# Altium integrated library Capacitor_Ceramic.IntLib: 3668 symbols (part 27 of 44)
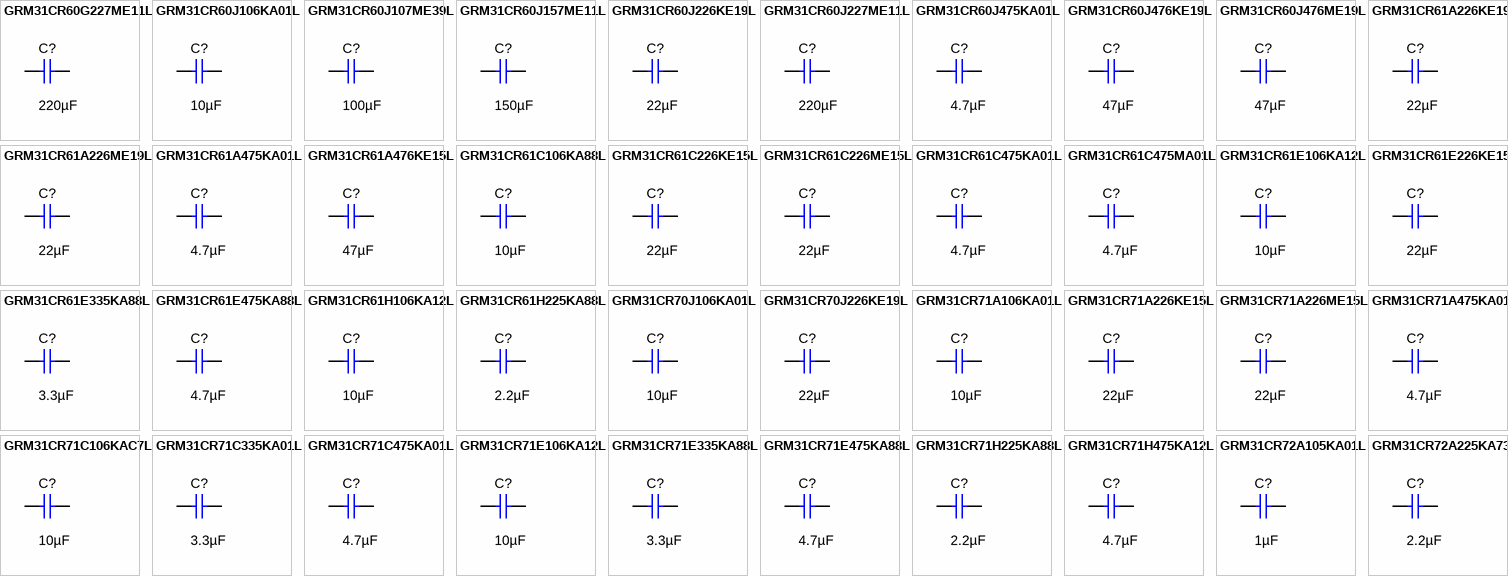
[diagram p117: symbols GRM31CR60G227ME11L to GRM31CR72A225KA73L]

## GRM31CR71H225KA88L
designator C?  ValueDisplayed: 2.2µF  (hidden comment: GRM31CR71H225KA88L)
CAP, CERM, 2.2 µF, 50 V,+/- 10%, X7R, 1206; Manufacturer: MuRata; Polarized: N; CompType: Capacitor; Value: 2.2uF; U/M: EA; Cap_F: 0.0000022; Tolerance_%: 10; VDC_V: 50; Value2: 50V; TaMin_C: -55; TaMax_C: 125; Cap_Case: 1206; SizeArea_mm2: 5.12; SizeAreaWB_mm2: 10.92; SizeX_mm: 3.2; SizeY_mm: 1.6; SizeZ_mm: 1.8; AEC Category: Q200; Green_Lifecycle: Active; Green_REACh: Passed
signal-integrity model Cap
simulation model Cap
footprint 1206_180
footprint 1206_180M
footprint 1206_180L
pins: 1, 2

## GRM31CR71H475KA12L
designator C?  ValueDisplayed: 4.7µF  (hidden comment: GRM31CR71H475KA12L)
CAP, CERM, 4.7 µF, 50 V,+/- 10%, X7R, 1206; Manufacturer: MuRata; Polarized: N; CompType: Capacitor; Value: 4.7uF; U/M: EA; Cap_F: 0.0000047; Tolerance_%: 10; VDC_V: 50; Value2: 50V; TaMin_C: -55; TaMax_C: 125; Cap_Case: 1206; SizeArea_mm2: 5.12; SizeAreaWB_mm2: 10.92; SizeX_mm: 3.2; SizeY_mm: 1.6; SizeZ_mm: 1.8; AEC Category: Q200; Green_Lifecycle: Active; Green_REACh: Passed
signal-integrity model Cap
simulation model Cap
footprint 1206_180
footprint 1206_180M
footprint 1206_180L
pins: 1, 2

## GRM31CR72A105KA01L
designator C?  ValueDisplayed: 1µF  (hidden comment: GRM31CR72A105KA01L)
CAP, CERM, 1 µF, 100 V,+/- 10%, X7R, 1206; Manufacturer: MuRata; Polarized: N; CompType: Capacitor; Value: 1uF; U/M: EA; Cap_F: 0.000001; Tolerance_%: 10; VDC_V: 100; Value2: 100V; TaMin_C: -55; TaMax_C: 125; Cap_Case: 1206; SizeArea_mm2: 5.12; SizeAreaWB_mm2: 10.92; SizeX_mm: 3.2; SizeY_mm: 1.6; SizeZ_mm: 1.8; AEC Category: Q200; Green_Lifecycle: Active; Green_REACh: Passed
signal-integrity model Cap
simulation model Cap
footprint 1206_180
footprint 1206_180M
footprint 1206_180L
pins: 1, 2

## GRM31CR72A225KA73L
designator C?  ValueDisplayed: 2.2µF  (hidden comment: GRM31CR72A225KA73L)
CAP, CERM, 2.2 µF, 100 V,+/- 10%, X7R, 1206; Manufacturer: MuRata; Polarized: N; CompType: Capacitor; Value: 2.2uF; U/M: EA; Cap_F: 0.0000022; Tolerance_%: 10; VDC_V: 100; Value2: 100V; TaMin_C: -55; TaMax_C: 125; Cap_Case: 1206; SizeArea_mm2: 5.12; SizeAreaWB_mm2: 10.92; SizeX_mm: 3.2; SizeY_mm: 1.6; SizeZ_mm: 1.9; AEC Category: Q200; Green_Lifecycle: Active; Green_REACh: Passed
signal-integrity model Cap
simulation model Cap
footprint 1206_190
footprint 1206_190M
footprint 1206_190L
pins: 1, 2

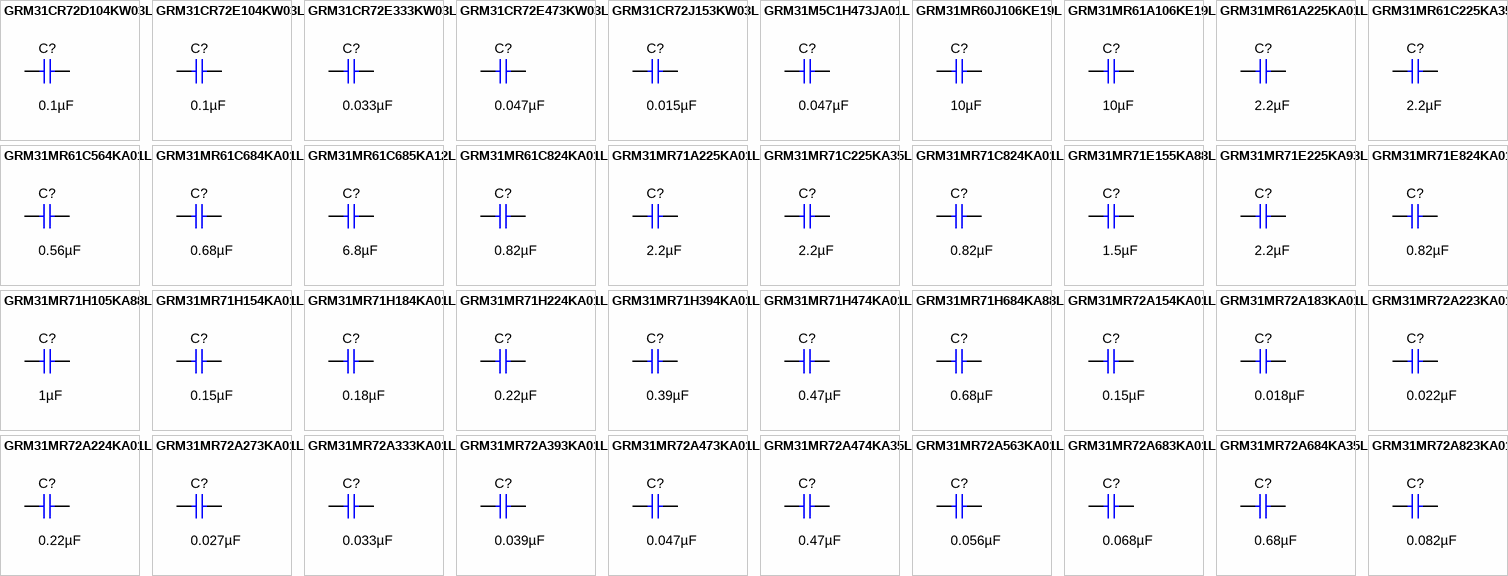
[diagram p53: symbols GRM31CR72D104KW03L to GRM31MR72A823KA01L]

## GRM31CR72D104KW03L
designator C?  ValueDisplayed: 0.1µF  (hidden comment: GRM31CR72D104KW03L)
CAP, CERM, 0.1 µF, 200 V,+/- 10%, X7R, 1206; Manufacturer: MuRata; Polarized: N; CompType: Capacitor; Value: 0.1uF; U/M: EA; Cap_F: 0.0000001; Tolerance_%: 10; VDC_V: 200; Value2: 200V; TaMin_C: -55; TaMax_C: 125; Cap_Case: 1206; SizeArea_mm2: 5.12; SizeAreaWB_mm2: 10.92; SizeX_mm: 3.2; SizeY_mm: 1.6; SizeZ_mm: 1.8; AEC Category: Q200
signal-integrity model Cap
simulation model Cap
footprint 1206_180
footprint 1206_180M
footprint 1206_180L
pins: 1, 2

## GRM31CR72E104KW03L
designator C?  ValueDisplayed: 0.1µF  (hidden comment: GRM31CR72E104KW03L)
CAP, CERM, 0.1 µF, 250 V,+/- 10%, X7R, 1206; Manufacturer: MuRata; Polarized: N; CompType: Capacitor; Value: 0.1uF; U/M: EA; Cap_F: 0.0000001; Tolerance_%: 10; VDC_V: 250; Value2: 250V; TaMin_C: -55; TaMax_C: 125; Cap_Case: 1206; SizeArea_mm2: 5.12; SizeAreaWB_mm2: 10.92; SizeX_mm: 3.2; SizeY_mm: 1.6; SizeZ_mm: 1.8; AEC Category: Q200; Green_Lifecycle: Active; Green_REACh: Passed
signal-integrity model Cap
simulation model Cap
footprint 1206_180
footprint 1206_180M
footprint 1206_180L
pins: 1, 2

## GRM31CR72E333KW03L
designator C?  ValueDisplayed: 0.033µF  (hidden comment: GRM31CR72E333KW03L)
CAP, CERM, 0.033 µF, 250 V,+/- 10%, X7R, 1206; Manufacturer: MuRata; Polarized: N; CompType: Capacitor; Value: 0.033uF; U/M: EA; Cap_F: 0.000000033; Tolerance_%: 10; VDC_V: 250; Value2: 250V; TaMin_C: -55; TaMax_C: 125; Cap_Case: 1206; SizeArea_mm2: 5.12; SizeAreaWB_mm2: 10.92; SizeX_mm: 3.2; SizeY_mm: 1.6; SizeZ_mm: 1.8; AEC Category: Q200
signal-integrity model Cap
simulation model Cap
footprint 1206_180
footprint 1206_180M
footprint 1206_180L
pins: 1, 2

## GRM31CR72E473KW03L
designator C?  ValueDisplayed: 0.047µF  (hidden comment: GRM31CR72E473KW03L)
CAP, CERM, 0.047 µF, 250 V,+/- 10%, X7R, 1206; Manufacturer: MuRata; Polarized: N; CompType: Capacitor; Value: 0.047uF; U/M: EA; Cap_F: 0.000000047; Tolerance_%: 10; VDC_V: 250; Value2: 250V; TaMin_C: -55; TaMax_C: 125; Cap_Case: 1206; SizeArea_mm2: 5.12; SizeAreaWB_mm2: 10.92; SizeX_mm: 3.2; SizeY_mm: 1.6; SizeZ_mm: 1.8; AEC Category: Q200
signal-integrity model Cap
simulation model Cap
footprint 1206_180
footprint 1206_180M
footprint 1206_180L
pins: 1, 2

## GRM31CR72J153KW03L
designator C?  ValueDisplayed: 0.015µF  (hidden comment: GRM31CR72J153KW03L)
CAP, CERM, 0.015 µF, 630 V,+/- 10%, X7R, 1206; Manufacturer: MuRata; Polarized: N; CompType: Capacitor; Value: 0.015uF; U/M: EA; Cap_F: 0.000000015; Tolerance_%: 10; VDC_V: 630; Value2: 630V; TaMin_C: -55; TaMax_C: 125; Cap_Case: 1206; SizeArea_mm2: 5.12; SizeAreaWB_mm2: 10.92; SizeX_mm: 3.2; SizeY_mm: 1.6; SizeZ_mm: 1.8; AEC Category: Q200
signal-integrity model Cap
simulation model Cap
footprint 1206_180
footprint 1206_180M
footprint 1206_180L
pins: 1, 2

## GRM31M5C1H473JA01L
designator C?  ValueDisplayed: 0.047µF  (hidden comment: GRM31M5C1H473JA01L)
CAP, CERM, 0.047 µF, 50 V,+/- 5%, C0G/NP0, 1206; Manufacturer: MuRata; Polarized: N; CompType: Capacitor; Value: 0.047uF; U/M: EA; Cap_F: 0.000000047; Tolerance_%: 5; VDC_V: 50; Value2: 50V; TaMin_C: -55; TaMax_C: 125; Cap_Case: 1206; SizeArea_mm2: 5.12; SizeAreaWB_mm2: 10.92; SizeX_mm: 3.2; SizeY_mm: 1.6; SizeZ_mm: 1.35; AEC Category: Q200; Green_Lifecycle: Active; Green_REACh: Passed
signal-integrity model Cap
simulation model Cap
footprint 1206
footprint 1206M
footprint 1206L
pins: 1, 2

## GRM31MR60J106KE19L
designator C?  ValueDisplayed: 10µF  (hidden comment: GRM31MR60J106KE19L)
CAP, CERM, 10 µF, 6.3 V,+/- 10%, X5R, 1206; Manufacturer: MuRata; Polarized: N; CompType: Capacitor; Value: 10uF; U/M: EA; Cap_F: 0.00001; Tolerance_%: 10; ESR_ohm: 0.005; Value1: 0.005 ohm; VDC_V: 6.3; Value2: 6.3V; TaMin_C: -55; TaMax_C: 85; Cap_Case: 1206; SizeArea_mm2: 5.12; SizeAreaWB_mm2: 10.92; SizeX_mm: 3.2; SizeY_mm: 1.6; SizeZ_mm: 1.35; AEC Category: Q200
signal-integrity model Cap
simulation model Cap
footprint 1206
footprint 1206M
footprint 1206L
pins: 1, 2

## GRM31MR61A106KE19L
designator C?  ValueDisplayed: 10µF  (hidden comment: GRM31MR61A106KE19L)
CAP, CERM, 10 µF, 10 V,+/- 10%, X5R, 1206; Manufacturer: MuRata; Polarized: N; CompType: Capacitor; Value: 10uF; U/M: EA; Cap_F: 0.00001; Tolerance_%: 10; Value2: 10V; TaMin_C: -55; TaMax_C: 85; Cap_Case: 1206; SizeArea_mm2: 5.12; SizeAreaWB_mm2: 10.92; SizeX_mm: 3.2; SizeY_mm: 1.6; SizeZ_mm: 1.35; AEC Category: Q200; Green_Lifecycle: Active; Green_REACh: Passed
signal-integrity model Cap
simulation model Cap
footprint 1206
footprint 1206M
footprint 1206L
pins: 1, 2

## GRM31MR61A225KA01L
designator C?  ValueDisplayed: 2.2µF  (hidden comment: GRM31MR61A225KA01L)
CAP, CERM, 2.2 µF, 10 V,+/- 10%, X5R, 1206; Manufacturer: MuRata; Polarized: N; CompType: Capacitor; Value: 2.2uF; U/M: EA; Cap_F: 0.0000022; Tolerance_%: 10; Value2: 10V; TaMin_C: -55; TaMax_C: 85; Cap_Case: 1206; SizeArea_mm2: 5.12; SizeAreaWB_mm2: 10.92; SizeX_mm: 3.2; SizeY_mm: 1.6; SizeZ_mm: 1.35; AEC Category: Q200
signal-integrity model Cap
simulation model Cap
footprint 1206
footprint 1206M
footprint 1206L
pins: 1, 2

## GRM31MR61C225KA35L
designator C?  ValueDisplayed: 2.2µF  (hidden comment: GRM31MR61C225KA35L)
CAP, CERM, 2.2 µF, 16 V,+/- 10%, X5R, 1206; Manufacturer: MuRata; Polarized: N; CompType: Capacitor; Value: 2.2uF; U/M: EA; Cap_F: 0.0000022; Tolerance_%: 10; VDC_V: 16; Value2: 16V; TaMin_C: -55; TaMax_C: 85; Cap_Case: 1206; SizeArea_mm2: 5.12; SizeAreaWB_mm2: 10.92; SizeX_mm: 3.2; SizeY_mm: 1.6; SizeZ_mm: 1.35; AEC Category: Q200
signal-integrity model Cap
simulation model Cap
footprint 1206
footprint 1206M
footprint 1206L
pins: 1, 2

## GRM31MR61C564KA01L
designator C?  ValueDisplayed: 0.56µF  (hidden comment: GRM31MR61C564KA01L)
CAP, CERM, 0.56 µF, 16 V,+/- 10%, X5R, 1206; Manufacturer: MuRata; Polarized: N; CompType: Capacitor; Value: 0.56uF; U/M: EA; Cap_F: 0.00000056; Tolerance_%: 10; VDC_V: 16; Value2: 16V; TaMin_C: -55; TaMax_C: 85; Cap_Case: 1206; SizeArea_mm2: 5.12; SizeAreaWB_mm2: 10.92; SizeX_mm: 3.2; SizeY_mm: 1.6; SizeZ_mm: 1.35; AEC Category: Q200
signal-integrity model Cap
simulation model Cap
footprint 1206
footprint 1206M
footprint 1206L
pins: 1, 2

## GRM31MR61C684KA01L
designator C?  ValueDisplayed: 0.68µF  (hidden comment: GRM31MR61C684KA01L)
CAP, CERM, 0.68 µF, 16 V,+/- 10%, X5R, 1206; Manufacturer: MuRata; Polarized: N; CompType: Capacitor; Value: 0.68uF; U/M: EA; Cap_F: 0.00000068; Tolerance_%: 10; VDC_V: 16; Value2: 16V; TaMin_C: -55; TaMax_C: 85; Cap_Case: 1206; SizeArea_mm2: 5.12; SizeAreaWB_mm2: 10.92; SizeX_mm: 3.2; SizeY_mm: 1.6; SizeZ_mm: 1.35; AEC Category: Q200
signal-integrity model Cap
simulation model Cap
footprint 1206
footprint 1206M
footprint 1206L
pins: 1, 2

## GRM31MR61C685KA12L
designator C?  ValueDisplayed: 6.8µF  (hidden comment: GRM31MR61C685KA12L)
CAP, CERM, 6.8 µF, 16 V,+/- 10%, X5R, 1206; Manufacturer: MuRata; Polarized: N; CompType: Capacitor; Value: 6.8uF; U/M: EA; Cap_F: 0.0000068; Tolerance_%: 10; VDC_V: 16; Value2: 16V; TaMin_C: -55; TaMax_C: 85; Cap_Case: 1206; SizeArea_mm2: 5.12; SizeAreaWB_mm2: 10.92; SizeX_mm: 3.2; SizeY_mm: 1.6; SizeZ_mm: 1.35; AEC Category: Q200
signal-integrity model Cap
simulation model Cap
footprint 1206
footprint 1206M
footprint 1206L
pins: 1, 2

## GRM31MR61C824KA01L
designator C?  ValueDisplayed: 0.82µF  (hidden comment: GRM31MR61C824KA01L)
CAP, CERM, 0.82 µF, 16 V,+/- 10%, X5R, 1206; Manufacturer: MuRata; Polarized: N; CompType: Capacitor; Value: 0.82uF; U/M: EA; Cap_F: 0.00000082; Tolerance_%: 10; VDC_V: 16; Value2: 16V; TaMin_C: -55; TaMax_C: 85; Cap_Case: 1206; SizeArea_mm2: 5.12; SizeAreaWB_mm2: 10.92; SizeX_mm: 3.2; SizeY_mm: 1.6; SizeZ_mm: 1.35; AEC Category: Q200
signal-integrity model Cap
simulation model Cap
footprint 1206
footprint 1206M
footprint 1206L
pins: 1, 2

## GRM31MR71A225KA01L
designator C?  ValueDisplayed: 2.2µF  (hidden comment: GRM31MR71A225KA01L)
CAP, CERM, 2.2 µF, 10 V,+/- 10%, X7R, 1206; Manufacturer: MuRata; Polarized: N; CompType: Capacitor; Value: 2.2uF; U/M: EA; Cap_F: 0.0000022; Tolerance_%: 10; Value2: 10V; TaMin_C: -55; TaMax_C: 125; Cap_Case: 1206; SizeArea_mm2: 5.12; SizeAreaWB_mm2: 10.92; SizeX_mm: 3.2; SizeY_mm: 1.6; SizeZ_mm: 1.35; AEC Category: Q200
signal-integrity model Cap
simulation model Cap
footprint 1206
footprint 1206M
footprint 1206L
pins: 1, 2

## GRM31MR71C225KA35L
designator C?  ValueDisplayed: 2.2µF  (hidden comment: GRM31MR71C225KA35L)
CAP, CERM, 2.2 µF, 16 V,+/- 10%, X7R, 1206; Manufacturer: MuRata; Polarized: N; CompType: Capacitor; Value: 2.2uF; U/M: EA; Cap_F: 0.0000022; Tolerance_%: 10; ESR_ohm: 0.006; Value1: 0.006 ohm; VDC_V: 16; Value2: 16V; TaMin_C: -55; TaMax_C: 125; Cap_Case: 1206; SizeArea_mm2: 5.12; SizeAreaWB_mm2: 10.92; SizeX_mm: 3.2; SizeY_mm: 1.6; SizeZ_mm: 1.35; AEC Category: Q200; Green_Lifecycle: Active; Green_REACh: Passed
signal-integrity model Cap
simulation model Cap
footprint 1206
footprint 1206M
footprint 1206L
pins: 1, 2

## GRM31MR71C824KA01L
designator C?  ValueDisplayed: 0.82µF  (hidden comment: GRM31MR71C824KA01L)
CAP, CERM, 0.82 µF, 16 V,+/- 10%, X7R, 1206; Manufacturer: MuRata; Polarized: N; CompType: Capacitor; Value: 0.82uF; U/M: EA; Cap_F: 0.00000082; Tolerance_%: 10; VDC_V: 16; Value2: 16V; TaMin_C: -55; TaMax_C: 125; Cap_Case: 1206; SizeArea_mm2: 5.12; SizeAreaWB_mm2: 10.92; SizeX_mm: 3.2; SizeY_mm: 1.6; SizeZ_mm: 1.35; AEC Category: Q200
signal-integrity model Cap
simulation model Cap
footprint 1206
footprint 1206M
footprint 1206L
pins: 1, 2

## GRM31MR71E155KA88L
designator C?  ValueDisplayed: 1.5µF  (hidden comment: GRM31MR71E155KA88L)
CAP, CERM, 1.5 µF, 25 V,+/- 10%, X7R, 1206; Manufacturer: MuRata; Polarized: N; CompType: Capacitor; Value: 1.5uF; U/M: EA; Cap_F: 0.0000015; Tolerance_%: 10; VDC_V: 25; Value2: 25V; TaMin_C: -55; TaMax_C: 125; Cap_Case: 1206; SizeArea_mm2: 5.12; SizeAreaWB_mm2: 10.92; SizeX_mm: 3.2; SizeY_mm: 1.6; SizeZ_mm: 1.35; AEC Category: Q200
signal-integrity model Cap
simulation model Cap
footprint 1206
footprint 1206M
footprint 1206L
pins: 1, 2

## GRM31MR71E225KA93L
designator C?  ValueDisplayed: 2.2µF  (hidden comment: GRM31MR71E225KA93L)
CAP, CERM, 2.2 µF, 25 V,+/- 10%, X7R, 1206; Manufacturer: MuRata; Polarized: N; CompType: Capacitor; Value: 2.2uF; U/M: EA; Cap_F: 0.0000022; Tolerance_%: 10; VDC_V: 25; Value2: 25V; TaMin_C: -55; TaMax_C: 125; Cap_Case: 1206; SizeArea_mm2: 5.12; SizeAreaWB_mm2: 10.92; SizeX_mm: 3.2; SizeY_mm: 1.6; SizeZ_mm: 1.35; AEC Category: Q200; Green_Lifecycle: Active; Green_REACh: Passed
signal-integrity model Cap
simulation model Cap
footprint 1206
footprint 1206M
footprint 1206L
pins: 1, 2

## GRM31MR71E824KA01L
designator C?  ValueDisplayed: 0.82µF  (hidden comment: GRM31MR71E824KA01L)
CAP, CERM, 0.82 µF, 25 V,+/- 10%, X7R, 1206; Manufacturer: MuRata; Polarized: N; CompType: Capacitor; Value: 0.82uF; U/M: EA; Cap_F: 0.00000082; Tolerance_%: 10; VDC_V: 25; Value2: 25V; TaMin_C: -55; TaMax_C: 125; Cap_Case: 1206; SizeArea_mm2: 5.12; SizeAreaWB_mm2: 10.92; SizeX_mm: 3.2; SizeY_mm: 1.6; SizeZ_mm: 1.35; AEC Category: Q200
signal-integrity model Cap
simulation model Cap
footprint 1206
footprint 1206M
footprint 1206L
pins: 1, 2

## GRM31MR71H105KA88L
designator C?  ValueDisplayed: 1µF  (hidden comment: GRM31MR71H105KA88L)
CAP, CERM, 1 µF, 50 V,+/- 10%, X7R, 1206; Manufacturer: MuRata; Polarized: N; CompType: Capacitor; Value: 1uF; U/M: EA; Cap_F: 0.000001; Tolerance_%: 10; VDC_V: 50; Value2: 50V; TaMin_C: -55; TaMax_C: 125; Cap_Case: 1206; SizeArea_mm2: 5.12; SizeAreaWB_mm2: 10.92; SizeX_mm: 3.2; SizeY_mm: 1.6; SizeZ_mm: 1.35; AEC Category: Q200; Green_Lifecycle: Active; Green_REACh: Passed
signal-integrity model Cap
simulation model Cap
footprint 1206
footprint 1206M
footprint 1206L
pins: 1, 2

## GRM31MR71H154KA01L
designator C?  ValueDisplayed: 0.15µF  (hidden comment: GRM31MR71H154KA01L)
CAP, CERM, 0.15 µF, 50 V,+/- 10%, X7R, 1206; Manufacturer: MuRata; Polarized: N; CompType: Capacitor; Value: 0.15uF; U/M: EA; Cap_F: 0.00000015; Tolerance_%: 10; VDC_V: 50; Value2: 50V; TaMin_C: -55; TaMax_C: 125; Cap_Case: 1206; SizeArea_mm2: 5.12; SizeAreaWB_mm2: 10.92; SizeX_mm: 3.2; SizeY_mm: 1.6; SizeZ_mm: 1.35; AEC Category: Q200
signal-integrity model Cap
simulation model Cap
footprint 1206
footprint 1206M
footprint 1206L
pins: 1, 2

## GRM31MR71H184KA01L
designator C?  ValueDisplayed: 0.18µF  (hidden comment: GRM31MR71H184KA01L)
CAP, CERM, 0.18 µF, 50 V,+/- 10%, X7R, 1206; Manufacturer: MuRata; Polarized: N; CompType: Capacitor; Value: 0.18uF; U/M: EA; Cap_F: 0.00000018; Tolerance_%: 10; VDC_V: 50; Value2: 50V; TaMin_C: -55; TaMax_C: 125; Cap_Case: 1206; SizeArea_mm2: 5.12; SizeAreaWB_mm2: 10.92; SizeX_mm: 3.2; SizeY_mm: 1.6; SizeZ_mm: 1.35; AEC Category: Q200
signal-integrity model Cap
simulation model Cap
footprint 1206
footprint 1206M
footprint 1206L
pins: 1, 2

## GRM31MR71H224KA01L
designator C?  ValueDisplayed: 0.22µF  (hidden comment: GRM31MR71H224KA01L)
CAP, CERM, 0.22 µF, 50 V,+/- 10%, X7R, 1206; Manufacturer: MuRata; Polarized: N; CompType: Capacitor; Value: 0.22uF; U/M: EA; Cap_F: 0.00000022; Tolerance_%: 10; VDC_V: 50; Value2: 50V; TaMin_C: -55; TaMax_C: 125; Cap_Case: 1206; SizeArea_mm2: 5.12; SizeAreaWB_mm2: 10.92; SizeX_mm: 3.2; SizeY_mm: 1.6; SizeZ_mm: 1.35; AEC Category: Q200
signal-integrity model Cap
simulation model Cap
footprint 1206
footprint 1206M
footprint 1206L
pins: 1, 2

## GRM31MR71H394KA01L
designator C?  ValueDisplayed: 0.39µF  (hidden comment: GRM31MR71H394KA01L)
CAP, CERM, 0.39 µF, 50 V,+/- 10%, X7R, 1206; Manufacturer: MuRata; Polarized: N; CompType: Capacitor; Value: 0.39uF; U/M: EA; Cap_F: 0.00000039; Tolerance_%: 10; VDC_V: 50; Value2: 50V; TaMin_C: -55; TaMax_C: 125; Cap_Case: 1206; SizeArea_mm2: 5.12; SizeAreaWB_mm2: 10.92; SizeX_mm: 3.2; SizeY_mm: 1.6; SizeZ_mm: 1.35; AEC Category: Q200
signal-integrity model Cap
simulation model Cap
footprint 1206
footprint 1206M
footprint 1206L
pins: 1, 2

## GRM31MR71H474KA01L
designator C?  ValueDisplayed: 0.47µF  (hidden comment: GRM31MR71H474KA01L)
CAP, CERM, 0.47 µF, 50 V,+/- 10%, X7R, 1206; Manufacturer: MuRata; Polarized: N; CompType: Capacitor; Value: 0.47uF; U/M: EA; Cap_F: 0.00000047; Tolerance_%: 10; VDC_V: 50; Value2: 50V; TaMin_C: -55; TaMax_C: 125; Cap_Case: 1206; SizeArea_mm2: 5.12; SizeAreaWB_mm2: 10.92; SizeX_mm: 3.2; SizeY_mm: 1.6; SizeZ_mm: 1.35; AEC Category: Q200
signal-integrity model Cap
simulation model Cap
footprint 1206
footprint 1206M
footprint 1206L
pins: 1, 2

## GRM31MR71H684KA88L
designator C?  ValueDisplayed: 0.68µF  (hidden comment: GRM31MR71H684KA88L)
CAP, CERM, 0.68 µF, 50 V,+/- 10%, X7R, 1206; Manufacturer: MuRata; Polarized: N; CompType: Capacitor; Value: 0.68uF; U/M: EA; Cap_F: 0.00000068; Tolerance_%: 10; VDC_V: 50; Value2: 50V; TaMin_C: -55; TaMax_C: 125; Cap_Case: 1206; SizeArea_mm2: 5.12; SizeAreaWB_mm2: 10.92; SizeX_mm: 3.2; SizeY_mm: 1.6; SizeZ_mm: 1.35; AEC Category: Q200; Green_Lifecycle: Active; Green_REACh: Passed
signal-integrity model Cap
simulation model Cap
footprint 1206
footprint 1206M
footprint 1206L
pins: 1, 2

## GRM31MR72A154KA01L
designator C?  ValueDisplayed: 0.15µF  (hidden comment: GRM31MR72A154KA01L)
CAP, CERM, 0.15 µF, 100 V,+/- 10%, X7R, 1206; Manufacturer: MuRata; Polarized: N; CompType: Capacitor; Value: 0.15uF; U/M: EA; Cap_F: 0.00000015; Tolerance_%: 10; VDC_V: 100; Value2: 100V; TaMin_C: -55; TaMax_C: 125; Cap_Case: 1206; SizeArea_mm2: 5.12; SizeAreaWB_mm2: 10.92; SizeX_mm: 3.2; SizeY_mm: 1.6; SizeZ_mm: 1.35; AEC Category: Q200
signal-integrity model Cap
simulation model Cap
footprint 1206
footprint 1206M
footprint 1206L
pins: 1, 2

## GRM31MR72A183KA01L
designator C?  ValueDisplayed: 0.018µF  (hidden comment: GRM31MR72A183KA01L)
CAP, CERM, 0.018 µF, 100 V,+/- 10%, X7R, 1206; Manufacturer: MuRata; Polarized: N; CompType: Capacitor; Value: 0.018uF; U/M: EA; Cap_F: 0.000000018; Tolerance_%: 10; VDC_V: 100; Value2: 100V; TaMin_C: -55; TaMax_C: 125; Cap_Case: 1206; SizeArea_mm2: 5.12; SizeAreaWB_mm2: 10.92; SizeX_mm: 3.2; SizeY_mm: 1.6; SizeZ_mm: 1.35; AEC Category: Q200
signal-integrity model Cap
simulation model Cap
footprint 1206
footprint 1206M
footprint 1206L
pins: 1, 2

## GRM31MR72A223KA01L
designator C?  ValueDisplayed: 0.022µF  (hidden comment: GRM31MR72A223KA01L)
CAP, CERM, 0.022 µF, 100 V,+/- 10%, X7R, 1206; Manufacturer: MuRata; Polarized: N; CompType: Capacitor; Value: 0.022uF; U/M: EA; Cap_F: 0.000000022; Tolerance_%: 10; VDC_V: 100; Value2: 100V; TaMin_C: -55; TaMax_C: 125; Cap_Case: 1206; SizeArea_mm2: 5.12; SizeAreaWB_mm2: 10.92; SizeX_mm: 3.2; SizeY_mm: 1.6; SizeZ_mm: 1.35; AEC Category: Q200
signal-integrity model Cap
simulation model Cap
footprint 1206
footprint 1206M
footprint 1206L
pins: 1, 2

## GRM31MR72A224KA01L
designator C?  ValueDisplayed: 0.22µF  (hidden comment: GRM31MR72A224KA01L)
CAP, CERM, 0.22 µF, 100 V,+/- 10%, X7R, 1206; Manufacturer: MuRata; Polarized: N; CompType: Capacitor; Value: 0.22uF; U/M: EA; Cap_F: 0.00000022; Tolerance_%: 10; VDC_V: 100; Value2: 100V; TaMin_C: -55; TaMax_C: 125; Cap_Case: 1206; SizeArea_mm2: 5.12; SizeAreaWB_mm2: 10.92; SizeX_mm: 3.2; SizeY_mm: 1.6; SizeZ_mm: 1.35; AEC Category: Q200
signal-integrity model Cap
simulation model Cap
footprint 1206
footprint 1206M
footprint 1206L
pins: 1, 2

## GRM31MR72A273KA01L
designator C?  ValueDisplayed: 0.027µF  (hidden comment: GRM31MR72A273KA01L)
CAP, CERM, 0.027 µF, 100 V,+/- 10%, X7R, 1206; Manufacturer: MuRata; Polarized: N; CompType: Capacitor; Value: 0.027uF; U/M: EA; Cap_F: 0.000000027; Tolerance_%: 10; VDC_V: 100; Value2: 100V; TaMin_C: -55; TaMax_C: 125; Cap_Case: 1206; SizeArea_mm2: 5.12; SizeAreaWB_mm2: 10.92; SizeX_mm: 3.2; SizeY_mm: 1.6; SizeZ_mm: 1.35; AEC Category: Q200
signal-integrity model Cap
simulation model Cap
footprint 1206
footprint 1206M
footprint 1206L
pins: 1, 2

## GRM31MR72A333KA01L
designator C?  ValueDisplayed: 0.033µF  (hidden comment: GRM31MR72A333KA01L)
CAP, CERM, 0.033 µF, 100 V,+/- 10%, X7R, 1206; Manufacturer: MuRata; Polarized: N; CompType: Capacitor; Value: 0.033uF; U/M: EA; Cap_F: 0.000000033; Tolerance_%: 10; VDC_V: 100; Value2: 100V; TaMin_C: -55; TaMax_C: 125; Cap_Case: 1206; SizeArea_mm2: 5.12; SizeAreaWB_mm2: 10.92; SizeX_mm: 3.2; SizeY_mm: 1.6; SizeZ_mm: 1.35; AEC Category: Q200
signal-integrity model Cap
simulation model Cap
footprint 1206
footprint 1206M
footprint 1206L
pins: 1, 2

## GRM31MR72A393KA01L
designator C?  ValueDisplayed: 0.039µF  (hidden comment: GRM31MR72A393KA01L)
CAP, CERM, 0.039 µF, 100 V,+/- 10%, X7R, 1206; Manufacturer: MuRata; Polarized: N; CompType: Capacitor; Value: 0.039uF; U/M: EA; Cap_F: 0.000000039; Tolerance_%: 10; VDC_V: 100; Value2: 100V; TaMin_C: -55; TaMax_C: 125; Cap_Case: 1206; SizeArea_mm2: 5.12; SizeAreaWB_mm2: 10.92; SizeX_mm: 3.2; SizeY_mm: 1.6; SizeZ_mm: 1.35; AEC Category: Q200
signal-integrity model Cap
simulation model Cap
footprint 1206
footprint 1206M
footprint 1206L
pins: 1, 2

## GRM31MR72A473KA01L
designator C?  ValueDisplayed: 0.047µF  (hidden comment: GRM31MR72A473KA01L)
CAP, CERM, 0.047 µF, 100 V,+/- 10%, X7R, 1206; Manufacturer: MuRata; Polarized: N; CompType: Capacitor; Value: 0.047uF; U/M: EA; Cap_F: 0.000000047; Tolerance_%: 10; VDC_V: 100; Value2: 100V; TaMin_C: -55; TaMax_C: 125; Cap_Case: 1206; SizeArea_mm2: 5.12; SizeAreaWB_mm2: 10.92; SizeX_mm: 3.2; SizeY_mm: 1.6; SizeZ_mm: 1.35; AEC Category: Q200
signal-integrity model Cap
simulation model Cap
footprint 1206
footprint 1206M
footprint 1206L
pins: 1, 2

## GRM31MR72A474KA35L
designator C?  ValueDisplayed: 0.47µF  (hidden comment: GRM31MR72A474KA35L)
CAP, CERM, 0.47 µF, 100 V,+/- 10%, X7R, 1206; Manufacturer: MuRata; Polarized: N; CompType: Capacitor; Value: 0.47uF; U/M: EA; Cap_F: 0.00000047; Tolerance_%: 10; VDC_V: 100; Value2: 100V; TaMin_C: -55; TaMax_C: 125; Cap_Case: 1206; SizeArea_mm2: 5.12; SizeAreaWB_mm2: 10.92; SizeX_mm: 3.2; SizeY_mm: 1.6; SizeZ_mm: 1.35; AEC Category: Q200
signal-integrity model Cap
simulation model Cap
footprint 1206
footprint 1206M
footprint 1206L
pins: 1, 2

## GRM31MR72A563KA01L
designator C?  ValueDisplayed: 0.056µF  (hidden comment: GRM31MR72A563KA01L)
CAP, CERM, 0.056 µF, 100 V,+/- 10%, X7R, 1206; Manufacturer: MuRata; Polarized: N; CompType: Capacitor; Value: 0.056uF; U/M: EA; Cap_F: 0.000000056; Tolerance_%: 10; VDC_V: 100; Value2: 100V; TaMin_C: -55; TaMax_C: 125; Cap_Case: 1206; SizeArea_mm2: 5.12; SizeAreaWB_mm2: 10.92; SizeX_mm: 3.2; SizeY_mm: 1.6; SizeZ_mm: 1.35; AEC Category: Q200
signal-integrity model Cap
simulation model Cap
footprint 1206
footprint 1206M
footprint 1206L
pins: 1, 2

## GRM31MR72A683KA01L
designator C?  ValueDisplayed: 0.068µF  (hidden comment: GRM31MR72A683KA01L)
CAP, CERM, 0.068 µF, 100 V,+/- 10%, X7R, 1206; Manufacturer: MuRata; Polarized: N; CompType: Capacitor; Value: 0.068uF; U/M: EA; Cap_F: 0.000000068; Tolerance_%: 10; ESR_ohm: 0.01; Value1: 0.01 ohm; VDC_V: 100; Value2: 100V; IRMS_A: 0.8; TaMin_C: -55; TaMax_C: 125; Cap_Case: 1206; SizeArea_mm2: 5.12; SizeAreaWB_mm2: 10.92; SizeX_mm: 3.2; SizeY_mm: 1.6; SizeZ_mm: 1.35; AEC Category: Q200
signal-integrity model Cap
simulation model Cap
footprint 1206
footprint 1206M
footprint 1206L
pins: 1, 2

## GRM31MR72A684KA35L
designator C?  ValueDisplayed: 0.68µF  (hidden comment: GRM31MR72A684KA35L)
CAP, CERM, 0.68 µF, 100 V,+/- 10%, X7R, 1206; Manufacturer: MuRata; Polarized: N; CompType: Capacitor; Value: 0.68uF; U/M: EA; Cap_F: 0.00000068; Tolerance_%: 10; VDC_V: 100; Value2: 100V; TaMin_C: -55; TaMax_C: 125; Cap_Case: 1206; SizeArea_mm2: 5.12; SizeAreaWB_mm2: 10.92; SizeX_mm: 3.2; SizeY_mm: 1.6; SizeZ_mm: 1.35; AEC Category: Q200
signal-integrity model Cap
simulation model Cap
footprint 1206
footprint 1206M
footprint 1206L
pins: 1, 2

## GRM31MR72A823KA01L
designator C?  ValueDisplayed: 0.082µF  (hidden comment: GRM31MR72A823KA01L)
CAP, CERM, 0.082 µF, 100 V,+/- 10%, X7R, 1206; Manufacturer: MuRata; Polarized: N; CompType: Capacitor; Value: 0.082uF; U/M: EA; Cap_F: 0.000000082; Tolerance_%: 10; VDC_V: 100; Value2: 100V; TaMin_C: -55; TaMax_C: 125; Cap_Case: 1206; SizeArea_mm2: 5.12; SizeAreaWB_mm2: 10.92; SizeX_mm: 3.2; SizeY_mm: 1.6; SizeZ_mm: 1.35; AEC Category: Q200
signal-integrity model Cap
simulation model Cap
footprint 1206
footprint 1206M
footprint 1206L
pins: 1, 2

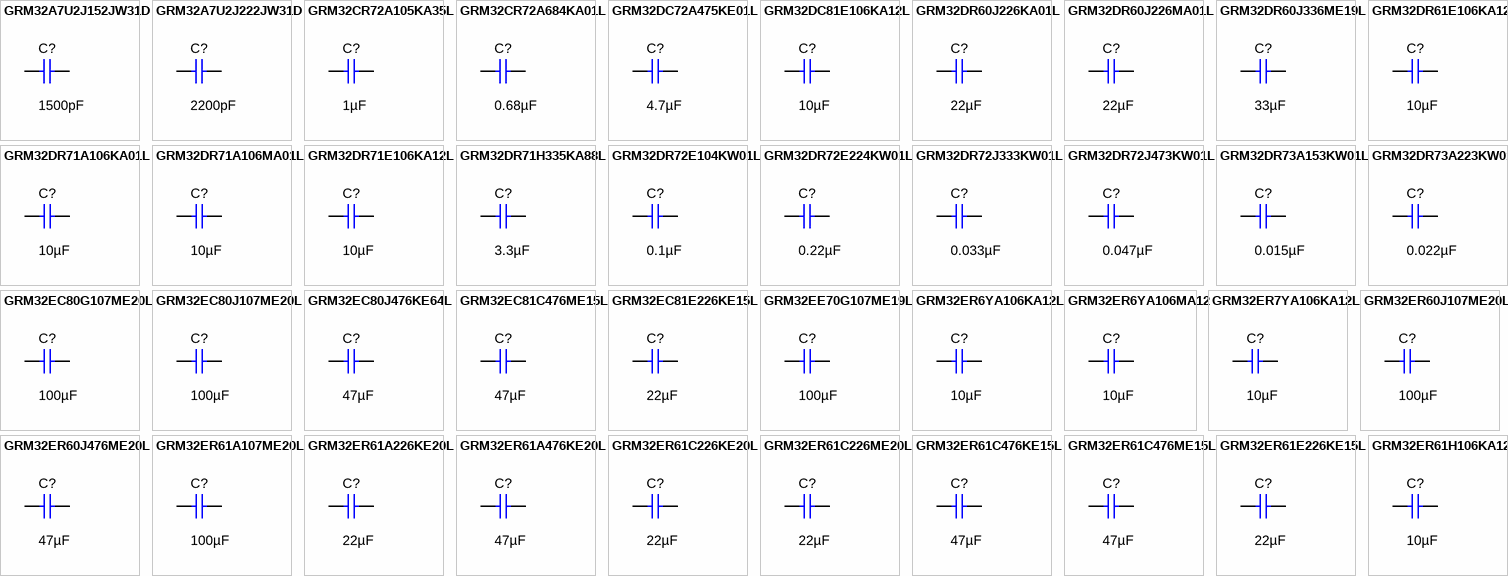
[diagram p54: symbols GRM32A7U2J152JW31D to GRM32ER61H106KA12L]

## GRM32A7U2J152JW31D
designator C?  ValueDisplayed: 1500pF  (hidden comment: GRM32A7U2J152JW31D)
CAP, CERM, 1500 pF, 630 V,+/- 5%, U2J, 1210; Manufacturer: MuRata; Polarized: N; CompType: Capacitor; Value: 1500pF; U/M: EA; Cap_F: 0.0000000015; Tolerance_%: 5; VDC_V: 630; Value2: 630V; TaMin_C: -55; TaMax_C: 125; Cap_Case: 1210; SizeArea_mm2: 8; SizeAreaWB_mm2: 14.7; SizeX_mm: 3.2; SizeY_mm: 2.5; SizeZ_mm: 1.35; AEC Category: Q200
signal-integrity model Cap
simulation model Cap
footprint 1210
footprint 1210M
footprint 1210L
pins: 1, 2

## GRM32A7U2J222JW31D
designator C?  ValueDisplayed: 2200pF  (hidden comment: GRM32A7U2J222JW31D)
CAP, CERM, 2200 pF, 630 V,+/- 5%, U2J, 1210; Manufacturer: MuRata; Polarized: N; CompType: Capacitor; Value: 2200pF; U/M: EA; Cap_F: 0.0000000022; Tolerance_%: 5; VDC_V: 630; Value2: 630V; TaMin_C: -55; TaMax_C: 125; Cap_Case: 1210; SizeArea_mm2: 8; SizeAreaWB_mm2: 14.7; SizeX_mm: 3.2; SizeY_mm: 2.5; SizeZ_mm: 1.35; AEC Category: Q200
signal-integrity model Cap
simulation model Cap
footprint 1210
footprint 1210M
footprint 1210L
pins: 1, 2

## GRM32CR72A105KA35L
designator C?  ValueDisplayed: 1µF  (hidden comment: GRM32CR72A105KA35L)
CAP, CERM, 1 µF, 100 V,+/- 10%, X7R, 1210; Manufacturer: MuRata; Polarized: N; CompType: Capacitor; Value: 1uF; U/M: EA; Cap_F: 0.000001; Tolerance_%: 10; VDC_V: 100; Value2: 100V; TaMin_C: -55; TaMax_C: 125; Cap_Case: 1210; SizeArea_mm2: 8; SizeAreaWB_mm2: 14.7; SizeX_mm: 3.2; SizeY_mm: 2.5; SizeZ_mm: 1.8; AEC Category: Q200; Green_Lifecycle: Active; Green_REACh: Passed
signal-integrity model Cap
simulation model Cap
footprint 1210_180
footprint 1210_180M
footprint 1210_180L
pins: 1, 2

## GRM32CR72A684KA01L
designator C?  ValueDisplayed: 0.68µF  (hidden comment: GRM32CR72A684KA01L)
CAP, CERM, 0.68 µF, 100 V,+/- 10%, X7R, 1210; Manufacturer: MuRata; Polarized: N; CompType: Capacitor; Value: 0.68uF; U/M: EA; Cap_F: 0.00000068; Tolerance_%: 10; VDC_V: 100; Value2: 100V; TaMin_C: -55; TaMax_C: 125; Cap_Case: 1210; SizeArea_mm2: 8; SizeAreaWB_mm2: 14.7; SizeX_mm: 3.2; SizeY_mm: 2.5; SizeZ_mm: 1.8; AEC Category: Q200
signal-integrity model Cap
simulation model Cap
footprint 1210_180
footprint 1210_180M
footprint 1210_180L
pins: 1, 2

## GRM32DC72A475KE01L
designator C?  ValueDisplayed: 4.7µF  (hidden comment: GRM32DC72A475KE01L)
CAP, CERM, 4.7 µF, 100 V,+/- 10%, X7S, 1210; Manufacturer: MuRata; Polarized: N; CompType: Capacitor; Value: 4.7uF; U/M: EA; Cap_F: 0.0000047; Tolerance_%: 10; VDC_V: 100; Value2: 100V; TaMin_C: -55; TaMax_C: 125; Cap_Case: 1210; SizeArea_mm2: 8; SizeAreaWB_mm2: 14.7; SizeX_mm: 3.2; SizeY_mm: 2.5; SizeZ_mm: 2.2; AEC Category: Q200
signal-integrity model Cap
simulation model Cap
footprint 1210_220
footprint 1210_220M
footprint 1210_220L
pins: 1, 2

## GRM32DC81E106KA12L
designator C?  ValueDisplayed: 10µF  (hidden comment: GRM32DC81E106KA12L)
CAP, CERM, 10 µF, 25 V,+/- 10%, X6S, 1210; Manufacturer: MuRata; Polarized: N; CompType: Capacitor; Value: 10uF; U/M: EA; Cap_F: 0.00001; Tolerance_%: 10; VDC_V: 25; Value2: 25V; TaMin_C: -55; TaMax_C: 105; Cap_Case: 1210; SizeArea_mm2: 8; SizeAreaWB_mm2: 14.7; SizeX_mm: 3.2; SizeY_mm: 2.5; SizeZ_mm: 2.2; AEC Category: Q200; Green_Lifecycle: Active; Green_REACh: Passed
signal-integrity model Cap
simulation model Cap
footprint 1210_220
footprint 1210_220M
footprint 1210_220L
pins: 1, 2

## GRM32DR60J226KA01L
designator C?  ValueDisplayed: 22µF  (hidden comment: GRM32DR60J226KA01L)
CAP, CERM, 22 µF, 6.3 V,+/- 10%, X5R, 1210; Manufacturer: MuRata; Polarized: N; CompType: Capacitor; Value: 22uF; U/M: EA; Cap_F: 0.000022; Tolerance_%: 10; ESR_ohm: 0.002; Value1: 0.002 ohm; VDC_V: 6.3; Value2: 6.3V; TaMin_C: -55; TaMax_C: 85; Cap_Case: 1210; SizeArea_mm2: 8; SizeAreaWB_mm2: 14.7; SizeX_mm: 3.2; SizeY_mm: 2.5; SizeZ_mm: 2.2; AEC Category: Q200
signal-integrity model Cap
simulation model Cap
footprint 1210_220
footprint 1210_220M
footprint 1210_220L
pins: 1, 2

## GRM32DR60J226MA01L
designator C?  ValueDisplayed: 22µF  (hidden comment: GRM32DR60J226MA01L)
CAP, CERM, 22 µF, 6.3 V,+/- 20%, X5R, 1210; Manufacturer: MuRata; Polarized: N; CompType: Capacitor; Value: 22uF; U/M: EA; Cap_F: 0.000022; Tolerance_%: 20; ESR_ohm: 0.002; Value1: 0.002 ohm; VDC_V: 6.3; Value2: 6.3V; TaMin_C: -55; TaMax_C: 85; Cap_Case: 1210; SizeArea_mm2: 8; SizeAreaWB_mm2: 14.7; SizeX_mm: 3.2; SizeY_mm: 2.5; SizeZ_mm: 2.2; AEC Category: Q200
signal-integrity model Cap
simulation model Cap
footprint 1210_220
footprint 1210_220M
footprint 1210_220L
pins: 1, 2

## GRM32DR60J336ME19L
designator C?  ValueDisplayed: 33µF  (hidden comment: GRM32DR60J336ME19L)
CAP, CERM, 33 µF, 6.3 V,+/- 20%, X5R, 1210; Manufacturer: MuRata; Polarized: N; CompType: Capacitor; Value: 33uF; U/M: EA; Cap_F: 0.000033; Tolerance_%: 20; ESR_ohm: 0.006; Value1: 0.006 ohm; VDC_V: 6.3; Value2: 6.3V; TaMin_C: -55; TaMax_C: 85; Cap_Case: 1210; SizeArea_mm2: 8; SizeAreaWB_mm2: 14.7; SizeX_mm: 3.2; SizeY_mm: 2.5; SizeZ_mm: 2.2; AEC Category: Q200; Green_Lifecycle: Active; Green_REACh: Passed
signal-integrity model Cap
simulation model Cap
footprint 1210_220
footprint 1210_220M
footprint 1210_220L
pins: 1, 2

## GRM32DR61E106KA12L
designator C?  ValueDisplayed: 10µF  (hidden comment: GRM32DR61E106KA12L)
CAP, CERM, 10 µF, 25 V,+/- 10%, X5R, 1210; Manufacturer: MuRata; Polarized: N; CompType: Capacitor; Value: 10uF; U/M: EA; Cap_F: 0.00001; Tolerance_%: 10; VDC_V: 25; Value2: 25V; TaMin_C: -55; TaMax_C: 85; Cap_Case: 1210; SizeArea_mm2: 8; SizeAreaWB_mm2: 14.7; SizeX_mm: 3.2; SizeY_mm: 2.5; SizeZ_mm: 2.2; AEC Category: Q200; Green_Lifecycle: Active; Green_REACh: Passed
signal-integrity model Cap
simulation model Cap
footprint 1210_220
footprint 1210_220M
footprint 1210_220L
pins: 1, 2

## GRM32DR71A106KA01L
designator C?  ValueDisplayed: 10µF  (hidden comment: GRM32DR71A106KA01L)
CAP, CERM, 10 µF, 10 V,+/- 10%, X7R, 1210; Manufacturer: MuRata; Polarized: N; CompType: Capacitor; Value: 10uF; U/M: EA; Cap_F: 0.00001; Tolerance_%: 10; Value2: 10V; TaMin_C: -55; TaMax_C: 125; Cap_Case: 1210; SizeArea_mm2: 8; SizeAreaWB_mm2: 14.7; SizeX_mm: 3.2; SizeY_mm: 2.5; SizeZ_mm: 2.2; AEC Category: Q200
signal-integrity model Cap
simulation model Cap
footprint 1210_220
footprint 1210_220M
footprint 1210_220L
pins: 1, 2

## GRM32DR71A106MA01L
designator C?  ValueDisplayed: 10µF  (hidden comment: GRM32DR71A106MA01L)
CAP, CERM, 10 µF, 10 V,+/- 20%, X7R, 1210; Manufacturer: MuRata; Polarized: N; CompType: Capacitor; Value: 10uF; U/M: EA; Cap_F: 0.00001; Tolerance_%: 20; VDC_V: 10; Value2: 10V; TaMin_C: -55; TaMax_C: 125; Cap_Case: 1210; SizeArea_mm2: 8; SizeAreaWB_mm2: 14.7; SizeX_mm: 3.2; SizeY_mm: 2.5; SizeZ_mm: 2.2; AEC Category: Q200
signal-integrity model Cap
simulation model Cap
footprint 1210_220
footprint 1210_220M
footprint 1210_220L
pins: 1, 2

## GRM32DR71E106KA12L
designator C?  ValueDisplayed: 10µF  (hidden comment: GRM32DR71E106KA12L)
CAP, CERM, 10 µF, 25 V,+/- 10%, X7R, 1210; Manufacturer: MuRata; Polarized: N; CompType: Capacitor; Value: 10uF; U/M: EA; Cap_F: 0.00001; Tolerance_%: 10; VDC_V: 25; Value2: 25V; TaMin_C: -55; TaMax_C: 125; Cap_Case: 1210; SizeArea_mm2: 8; SizeAreaWB_mm2: 14.7; SizeX_mm: 3.2; SizeY_mm: 2.5; SizeZ_mm: 2.2; AEC Category: Q200
signal-integrity model Cap
simulation model Cap
footprint 1210_220
footprint 1210_220M
footprint 1210_220L
pins: 1, 2

## GRM32DR71H335KA88L
designator C?  ValueDisplayed: 3.3µF  (hidden comment: GRM32DR71H335KA88L)
CAP, CERM, 3.3 µF, 50 V,+/- 10%, X7R, 1210; Manufacturer: MuRata; Polarized: N; CompType: Capacitor; Value: 3.3uF; U/M: EA; Cap_F: 0.0000033; Tolerance_%: 10; ESR_ohm: 0.003; Value1: 0.003 ohm; VDC_V: 50; Value2: 50V; TaMin_C: -55; TaMax_C: 125; Cap_Case: 1210; SizeArea_mm2: 8; SizeAreaWB_mm2: 14.7; SizeX_mm: 3.2; SizeY_mm: 2.5; SizeZ_mm: 2.2; AEC Category: Q200; Green_Lifecycle: Active; Green_REACh: Passed
signal-integrity model Cap
simulation model Cap
footprint 1210_220
footprint 1210_220M
footprint 1210_220L
pins: 1, 2

## GRM32DR72E104KW01L
designator C?  ValueDisplayed: 0.1µF  (hidden comment: GRM32DR72E104KW01L)
CAP, CERM, 0.1 µF, 250 V,+/- 10%, X7R, 1210; Manufacturer: MuRata; Polarized: N; CompType: Capacitor; Value: 0.1uF; U/M: EA; Cap_F: 0.0000001; Tolerance_%: 10; VDC_V: 250; Value2: 250V; TaMin_C: -55; TaMax_C: 125; Cap_Case: 1210; SizeArea_mm2: 8; SizeAreaWB_mm2: 14.7; SizeX_mm: 3.2; SizeY_mm: 2.5; SizeZ_mm: 2.2; AEC Category: Q200
signal-integrity model Cap
simulation model Cap
footprint 1210_220
footprint 1210_220M
footprint 1210_220L
pins: 1, 2

## GRM32DR72E224KW01L
designator C?  ValueDisplayed: 0.22µF  (hidden comment: GRM32DR72E224KW01L)
CAP, CERM, 0.22 µF, 250 V,+/- 10%, X7R, 1210; Manufacturer: MuRata; Polarized: N; CompType: Capacitor; Value: 0.22uF; U/M: EA; Cap_F: 0.00000022; Tolerance_%: 10; VDC_V: 250; Value2: 250V; TaMin_C: -55; TaMax_C: 125; Cap_Case: 1210; SizeArea_mm2: 8; SizeAreaWB_mm2: 14.7; SizeX_mm: 3.2; SizeY_mm: 2.5; SizeZ_mm: 2.2; AEC Category: Q200; Green_Lifecycle: Not Set; Green_REACh: Incomplete
signal-integrity model Cap
simulation model Cap
footprint 1210_220
footprint 1210_220M
footprint 1210_220L
pins: 1, 2

## GRM32DR72J333KW01L
designator C?  ValueDisplayed: 0.033µF  (hidden comment: GRM32DR72J333KW01L)
CAP, CERM, 0.033 µF, 630 V,+/- 10%, X7R, 1210; Manufacturer: MuRata; Polarized: N; CompType: Capacitor; Value: 0.033uF; U/M: EA; Cap_F: 0.000000033; Tolerance_%: 10; VDC_V: 630; Value2: 630V; TaMin_C: -55; TaMax_C: 125; Cap_Case: 1210; SizeArea_mm2: 8; SizeAreaWB_mm2: 14.7; SizeX_mm: 3.2; SizeY_mm: 2.5; SizeZ_mm: 2.2; AEC Category: Q200
signal-integrity model Cap
simulation model Cap
footprint 1210_220
footprint 1210_220M
footprint 1210_220L
pins: 1, 2

## GRM32DR72J473KW01L
designator C?  ValueDisplayed: 0.047µF  (hidden comment: GRM32DR72J473KW01L)
CAP, CERM, 0.047 µF, 630 V,+/- 10%, X7R, 1210; Manufacturer: MuRata; Polarized: N; CompType: Capacitor; Value: 0.047uF; U/M: EA; Cap_F: 0.000000047; Tolerance_%: 10; VDC_V: 630; Value2: 630V; TaMin_C: -55; TaMax_C: 125; Cap_Case: 1210; SizeArea_mm2: 8; SizeAreaWB_mm2: 14.7; SizeX_mm: 3.2; SizeY_mm: 2.5; SizeZ_mm: 2.2; AEC Category: Q200
signal-integrity model Cap
simulation model Cap
footprint 1210_220
footprint 1210_220M
footprint 1210_220L
pins: 1, 2

## GRM32DR73A153KW01L
designator C?  ValueDisplayed: 0.015µF  (hidden comment: GRM32DR73A153KW01L)
CAP, CERM, 0.015 µF, 1000 V,+/- 10%, X7R, 1210; Manufacturer: MuRata; Polarized: N; CompType: Capacitor; Value: 0.015uF; U/M: EA; Cap_F: 0.000000015; Tolerance_%: 10; VDC_V: 1000; Value2: 1000V; TaMin_C: -55; TaMax_C: 125; Cap_Case: 1210; SizeArea_mm2: 8; SizeAreaWB_mm2: 14.7; SizeX_mm: 3.2; SizeY_mm: 2.5; SizeZ_mm: 2.2; AEC Category: Q200
signal-integrity model Cap
simulation model Cap
footprint 1210_220
footprint 1210_220M
footprint 1210_220L
pins: 1, 2

## GRM32DR73A223KW01L
designator C?  ValueDisplayed: 0.022µF  (hidden comment: GRM32DR73A223KW01L)
CAP, CERM, 0.022 µF, 1000 V,+/- 10%, X7R, 1210; Manufacturer: MuRata; Polarized: N; CompType: Capacitor; Value: 0.022uF; U/M: EA; Cap_F: 0.000000022; Tolerance_%: 10; VDC_V: 1000; Value2: 1000V; TaMin_C: -55; TaMax_C: 125; Cap_Case: 1210; SizeArea_mm2: 8; SizeAreaWB_mm2: 14.7; SizeX_mm: 3.2; SizeY_mm: 2.5; SizeZ_mm: 2.2; AEC Category: Q200
signal-integrity model Cap
simulation model Cap
footprint 1210_220
footprint 1210_220M
footprint 1210_220L
pins: 1, 2

## GRM32EC80G107ME20L
designator C?  ValueDisplayed: 100µF  (hidden comment: GRM32EC80G107ME20L)
CAP, CERM, 100 µF, 4 V,+/- 20%, X6S, 1210; Manufacturer: MuRata; Polarized: N; CompType: Capacitor; Value: 100uF; U/M: EA; Cap_F: 0.0001; Tolerance_%: 20; VDC_V: 4; Value2: 4V; TaMin_C: -55; TaMax_C: 105; Cap_Case: 1210; SizeArea_mm2: 8; SizeAreaWB_mm2: 14.7; SizeX_mm: 3.2; SizeY_mm: 2.5; SizeZ_mm: 2.7; AEC Category: Q200
signal-integrity model Cap
simulation model Cap
footprint 1210_270
footprint 1210_270M
footprint 1210_270L
pins: 1, 2

## GRM32EC80J107ME20L
designator C?  ValueDisplayed: 100µF  (hidden comment: GRM32EC80J107ME20L)
CAP, CERM, 100 µF, 6.3 V,+/- 20%, X6S, 1210; Manufacturer: MuRata; Polarized: N; CompType: Capacitor; Value: 100uF; U/M: EA; Cap_F: 0.0001; Tolerance_%: 20; VDC_V: 6.3; Value2: 6.3V; TaMin_C: -55; TaMax_C: 105; Cap_Case: 1210; SizeArea_mm2: 8; SizeAreaWB_mm2: 14.7; SizeX_mm: 3.2; SizeY_mm: 2.5; SizeZ_mm: 2.7; AEC Category: Q200; Green_Lifecycle: Active; Green_REACh: Passed
signal-integrity model Cap
simulation model Cap
footprint 1210_270
footprint 1210_270M
footprint 1210_270L
pins: 1, 2

## GRM32EC80J476KE64L
designator C?  ValueDisplayed: 47µF  (hidden comment: GRM32EC80J476KE64L)
CAP, CERM, 47 µF, 6.3 V,+/- 10%, X6S, 1210; Manufacturer: MuRata; Polarized: N; CompType: Capacitor; Value: 47uF; U/M: EA; Cap_F: 0.000047; Tolerance_%: 10; VDC_V: 6.3; Value2: 6.3V; TaMin_C: -55; TaMax_C: 105; Cap_Case: 1210; SizeArea_mm2: 8; SizeAreaWB_mm2: 14.7; SizeX_mm: 3.2; SizeY_mm: 2.5; SizeZ_mm: 2.7; AEC Category: Q200
signal-integrity model Cap
simulation model Cap
footprint 1210_270
footprint 1210_270M
footprint 1210_270L
pins: 1, 2

## GRM32EC81C476ME15L
designator C?  ValueDisplayed: 47µF  (hidden comment: GRM32EC81C476ME15L)
CAP, CERM, 47 µF, 16 V,+/- 20%, X6S, 1210; Manufacturer: MuRata; Polarized: N; CompType: Capacitor; Value: 47uF; U/M: EA; Cap_F: 0.000047; Tolerance_%: 20; VDC_V: 16; Value2: 16V; TaMin_C: -55; TaMax_C: 105; Cap_Case: 1210; SizeArea_mm2: 8; SizeAreaWB_mm2: 14.7; SizeX_mm: 3.2; SizeY_mm: 2.5; SizeZ_mm: 2.7; AEC Category: Q200
signal-integrity model Cap
simulation model Cap
footprint 1210_270
footprint 1210_270M
footprint 1210_270L
pins: 1, 2

## GRM32EC81E226KE15L
designator C?  ValueDisplayed: 22µF  (hidden comment: GRM32EC81E226KE15L)
CAP, CERM, 22 µF, 25 V,+/- 10%, X6S, 1210; Manufacturer: MuRata; Polarized: N; CompType: Capacitor; Value: 22uF; U/M: EA; Cap_F: 0.000022; Tolerance_%: 10; VDC_V: 25; Value2: 25V; TaMin_C: -55; TaMax_C: 105; Cap_Case: 1210; SizeArea_mm2: 8; SizeAreaWB_mm2: 14.7; SizeX_mm: 3.2; SizeY_mm: 2.5; SizeZ_mm: 2.7; AEC Category: Q200; Green_Lifecycle: Active; Green_REACh: Passed
signal-integrity model Cap
simulation model Cap
footprint 1210_270
footprint 1210_270M
footprint 1210_270L
pins: 1, 2

## GRM32EE70G107ME19L
designator C?  ValueDisplayed: 100µF  (hidden comment: GRM32EE70G107ME19L)
CAP, CERM, 100 µF, 4 V,+/- 20%, X7U, 1210; Manufacturer: MuRata; Polarized: N; CompType: Capacitor; Value: 100uF; U/M: EA; Cap_F: 0.0001; Tolerance_%: 20; VDC_V: 4; Value2: 4V; TaMin_C: -55; TaMax_C: 125; Cap_Case: 1210; SizeArea_mm2: 8; SizeAreaWB_mm2: 14.7; SizeX_mm: 3.2; SizeY_mm: 2.5; SizeZ_mm: 2.7; AEC Category: Q200
signal-integrity model Cap
simulation model Cap
footprint 1210_270
footprint 1210_270M
footprint 1210_270L
pins: 1, 2

## GRM32ER6YA106KA12L
designator C?  ValueDisplayed: 10µF  (hidden comment: GRM32ER6YA106KA12L)
CAP, CERM, 10 µF, 35 V,+/- 10%, X5R, 1210; Manufacturer: MuRata; Polarized: N; CompType: Capacitor; Value: 10uF; U/M: EA; Cap_F: 0.00001; Tolerance_%: 10; VDC_V: 35; Value2: 35V; TaMin_C: -55; TaMax_C: 85; Cap_Case: 1210; SizeArea_mm2: 8; SizeAreaWB_mm2: 14.7; SizeX_mm: 3.2; SizeY_mm: 2.5; SizeZ_mm: 2.7; AEC Category: Q200
signal-integrity model Cap
simulation model Cap
footprint 1210_270
footprint 1210_270M
footprint 1210_270L
pins: 1, 2

## GRM32ER6YA106MA12
designator C?  ValueDisplayed: 10µF  (hidden comment: GRM32ER6YA106MA12)
CAP, CERM, 10 µF, 35 V,+/- 20%, X5R, 1210; Manufacturer: MuRata; Polarized: N; CompType: Capacitor; Value: 10uF; U/M: EA; Cap_F: 0.00001; Tolerance_%: 20; VDC_V: 35; Value2: 35V; TaMin_C: -55; TaMax_C: 85; Cap_Case: 1210; SizeArea_mm2: 8; SizeAreaWB_mm2: 14.7; SizeX_mm: 3.2; SizeY_mm: 2.5; SizeZ_mm: 2.7; AEC Category: Q200
signal-integrity model Cap
simulation model Cap
footprint 1210_270
footprint 1210_270M
footprint 1210_270L
pins: 1, 2

## GRM32ER7YA106KA12L
designator C?  ValueDisplayed: 10µF  (hidden comment: GRM32ER7YA106KA12L)
CAP, CERM, 10 µF, 35 V,+/- 10%, X7R, 1210; Manufacturer: MuRata; Polarized: N; CompType: Capacitor; Value: 10uF; U/M: EA; Cap_F: 0.00001; Tolerance_%: 10; VDC_V: 35; Value2: 35V; TaMin_C: -55; TaMax_C: 125; Cap_Case: 1210; SizeArea_mm2: 8; SizeAreaWB_mm2: 14.7; SizeX_mm: 3.2; SizeY_mm: 2.5; SizeZ_mm: 2.7; AEC Category: Q200; Green_Lifecycle: Active; Green_REACh: Passed
signal-integrity model Cap
simulation model Cap
footprint 1210_270
footprint 1210_270M
footprint 1210_270L
pins: 1, 2

## GRM32ER60J107ME20L
designator C?  ValueDisplayed: 100µF  (hidden comment: GRM32ER60J107ME20L)
CAP, CERM, 100 µF, 6.3 V,+/- 20%, X5R, 1210; Manufacturer: MuRata; Polarized: N; CompType: Capacitor; Value: 100uF; U/M: EA; Cap_F: 0.0001; Tolerance_%: 20; ESR_ohm: 0.002; Value1: 0.002 ohm; VDC_V: 6.3; Value2: 6.3V; TaMin_C: -55; TaMax_C: 85; Cap_Case: 1210; SizeArea_mm2: 8; SizeAreaWB_mm2: 14.7; SizeX_mm: 3.2; SizeY_mm: 2.5; SizeZ_mm: 2.7; AEC Category: Q200; Green_Lifecycle: Active; Green_REACh: Passed
signal-integrity model Cap
simulation model Cap
footprint 1210_270
footprint 1210_270M
footprint 1210_270L
pins: 1, 2

## GRM32ER60J476ME20L
designator C?  ValueDisplayed: 47µF  (hidden comment: GRM32ER60J476ME20L)
CAP, CERM, 47 µF, 6.3 V,+/- 20%, X5R, 1210; Manufacturer: MuRata; Polarized: N; CompType: Capacitor; Value: 47uF; U/M: EA; Cap_F: 0.000047; Tolerance_%: 20; ESR_ohm: 0.003; Value1: 0.003 ohm; VDC_V: 6.3; Value2: 6.3V; TaMin_C: -55; TaMax_C: 85; Cap_Case: 1210; SizeArea_mm2: 8; SizeAreaWB_mm2: 14.7; SizeX_mm: 3.2; SizeY_mm: 2.5; SizeZ_mm: 2.7; AEC Category: Q200; Green_Lifecycle: Active; Green_REACh: Passed
signal-integrity model Cap
simulation model Cap
footprint 1210_270
footprint 1210_270M
footprint 1210_270L
pins: 1, 2

## GRM32ER61A107ME20L
designator C?  ValueDisplayed: 100µF  (hidden comment: GRM32ER61A107ME20L)
CAP, CERM, 100 µF, 10 V,+/- 20%, X5R, 1210; Manufacturer: MuRata; Polarized: N; CompType: Capacitor; Value: 100uF; U/M: EA; Cap_F: 0.0001; Tolerance_%: 20; VDC_V: 10; Value2: 10V; TaMin_C: -55; TaMax_C: 85; Cap_Case: 1210; SizeArea_mm2: 8; SizeAreaWB_mm2: 14.7; SizeX_mm: 3.2; SizeY_mm: 2.5; SizeZ_mm: 2.7; AEC Category: Q200
signal-integrity model Cap
simulation model Cap
footprint 1210_270
footprint 1210_270M
footprint 1210_270L
pins: 1, 2

## GRM32ER61A226KE20L
designator C?  ValueDisplayed: 22µF  (hidden comment: GRM32ER61A226KE20L)
CAP, CERM, 22 µF, 10 V,+/- 10%, X5R, 1210; Manufacturer: MuRata; Polarized: N; CompType: Capacitor; Value: 22uF; U/M: EA; Cap_F: 0.000022; Tolerance_%: 10; ESR_ohm: 0.002; Value1: 0.002 ohm; Value2: 10V; TaMin_C: -55; TaMax_C: 85; Cap_Case: 1210; SizeArea_mm2: 8; SizeAreaWB_mm2: 14.7; SizeX_mm: 3.2; SizeY_mm: 2.5; SizeZ_mm: 2.7; AEC Category: Q200; Green_Lifecycle: Active; Green_REACh: Passed
signal-integrity model Cap
simulation model Cap
footprint 1210_270
footprint 1210_270M
footprint 1210_270L
pins: 1, 2

## GRM32ER61A476KE20L
designator C?  ValueDisplayed: 47µF  (hidden comment: GRM32ER61A476KE20L)
CAP, CERM, 47 µF, 10 V,+/- 10%, X5R, 1210; Manufacturer: MuRata; Polarized: N; CompType: Capacitor; Value: 47uF; U/M: EA; Cap_F: 0.000047; Tolerance_%: 10; ESR_ohm: 0.001; Value1: 0.001 ohm; Value2: 10V; TaMin_C: -55; TaMax_C: 85; Cap_Case: 1210; SizeArea_mm2: 8; SizeAreaWB_mm2: 14.7; SizeX_mm: 3.2; SizeY_mm: 2.5; SizeZ_mm: 2.7; AEC Category: Q200; Green_Lifecycle: Active; Green_REACh: Passed
signal-integrity model Cap
simulation model Cap
footprint 1210_270
footprint 1210_270M
footprint 1210_270L
pins: 1, 2

## GRM32ER61C226KE20L
designator C?  ValueDisplayed: 22µF  (hidden comment: GRM32ER61C226KE20L)
CAP, CERM, 22 µF, 16 V,+/- 10%, X5R, 1210; Manufacturer: MuRata; Polarized: N; CompType: Capacitor; Value: 22uF; U/M: EA; Cap_F: 0.000022; Tolerance_%: 10; ESR_ohm: 0.002; Value1: 0.002 ohm; VDC_V: 16; Value2: 16V; IRMS_A: 3.68; TaMin_C: -55; TaMax_C: 85; Cap_Case: 1210; SizeArea_mm2: 8; SizeAreaWB_mm2: 14.7; SizeX_mm: 3.2; SizeY_mm: 2.5; SizeZ_mm: 2.7; AEC Category: Q200; Green_Lifecycle: Active; Green_REACh: Passed
signal-integrity model Cap
simulation model Cap
footprint 1210_270
footprint 1210_270M
footprint 1210_270L
pins: 1, 2

## GRM32ER61C226ME20L
designator C?  ValueDisplayed: 22µF  (hidden comment: GRM32ER61C226ME20L)
CAP, CERM, 22 µF, 16 V,+/- 20%, X5R, 1210; Manufacturer: MuRata; Polarized: N; CompType: Capacitor; Value: 22uF; U/M: EA; Cap_F: 0.000022; Tolerance_%: 20; ESR_ohm: 0.002; Value1: 0.002 ohm; VDC_V: 16; Value2: 16V; IRMS_A: 3.68; TaMin_C: -55; TaMax_C: 85; Cap_Case: 1210; SizeArea_mm2: 8; SizeAreaWB_mm2: 14.7; SizeX_mm: 3.2; SizeY_mm: 2.5; SizeZ_mm: 2.7; AEC Category: Q200; Green_Lifecycle: Active; Green_REACh: Passed
signal-integrity model Cap
simulation model Cap
footprint 1210_270
footprint 1210_270M
footprint 1210_270L
pins: 1, 2

## GRM32ER61C476KE15L
designator C?  ValueDisplayed: 47µF  (hidden comment: GRM32ER61C476KE15L)
CAP, CERM, 47 µF, 16 V,+/- 10%, X5R, 1210; Manufacturer: MuRata; Polarized: N; CompType: Capacitor; Value: 47uF; U/M: EA; Cap_F: 0.000047; Tolerance_%: 10; VDC_V: 16; Value2: 16V; TaMin_C: -55; TaMax_C: 85; Cap_Case: 1210; SizeArea_mm2: 8; SizeAreaWB_mm2: 14.7; SizeX_mm: 3.2; SizeY_mm: 2.5; SizeZ_mm: 2.7; AEC Category: Q200; Green_Lifecycle: Active; Green_REACh: Passed
signal-integrity model Cap
simulation model Cap
footprint 1210_270
footprint 1210_270M
footprint 1210_270L
pins: 1, 2

## GRM32ER61C476ME15L
designator C?  ValueDisplayed: 47µF  (hidden comment: GRM32ER61C476ME15L)
CAP, CERM, 47 µF, 16 V,+/- 20%, X5R, 1210; Manufacturer: MuRata; Polarized: N; CompType: Capacitor; Value: 47uF; U/M: EA; Cap_F: 0.000047; Tolerance_%: 20; ESR_ohm: 0.002; Value1: 0.002 ohm; VDC_V: 16; Value2: 16V; TaMin_C: -55; TaMax_C: 85; Cap_Case: 1210; SizeArea_mm2: 8; SizeAreaWB_mm2: 14.7; SizeX_mm: 3.2; SizeY_mm: 2.5; SizeZ_mm: 2.7; AEC Category: Q200; Green_Lifecycle: Active; Green_REACh: Passed
signal-integrity model Cap
simulation model Cap
footprint 1210_270
footprint 1210_270M
footprint 1210_270L
pins: 1, 2

## GRM32ER61E226KE15L
designator C?  ValueDisplayed: 22µF  (hidden comment: GRM32ER61E226KE15L)
CAP, CERM, 22 µF, 25 V,+/- 10%, X5R, 1210; Manufacturer: MuRata; Polarized: N; CompType: Capacitor; Value: 22uF; U/M: EA; Cap_F: 0.000022; Tolerance_%: 10; ESR_ohm: 0.002; Value1: 0.002 ohm; VDC_V: 25; Value2: 25V; IRMS_A: 3.67; TaMin_C: -55; TaMax_C: 85; Cap_Case: 1210; SizeArea_mm2: 8; SizeAreaWB_mm2: 14.7; SizeX_mm: 3.2; SizeY_mm: 2.5; SizeZ_mm: 2.7; AEC Category: Q200; Green_Lifecycle: Active; Green_REACh: Passed
signal-integrity model Cap
simulation model Cap
footprint 1210_270
footprint 1210_270M
footprint 1210_270L
pins: 1, 2

## GRM32ER61H106KA12L
designator C?  ValueDisplayed: 10µF  (hidden comment: GRM32ER61H106KA12L)
CAP, CERM, 10 µF, 50 V,+/- 10%, X5R, 1210; Manufacturer: MuRata; Polarized: N; CompType: Capacitor; Value: 10uF; U/M: EA; Cap_F: 0.00001; Tolerance_%: 10; VDC_V: 50; Value2: 50V; TaMin_C: -55; TaMax_C: 85; Cap_Case: 1210; SizeArea_mm2: 8; SizeAreaWB_mm2: 14.7; SizeX_mm: 3.2; SizeY_mm: 2.5; SizeZ_mm: 2.7; AEC Category: Q200
signal-integrity model Cap
simulation model Cap
footprint 1210_270
footprint 1210_270M
footprint 1210_270L
pins: 1, 2

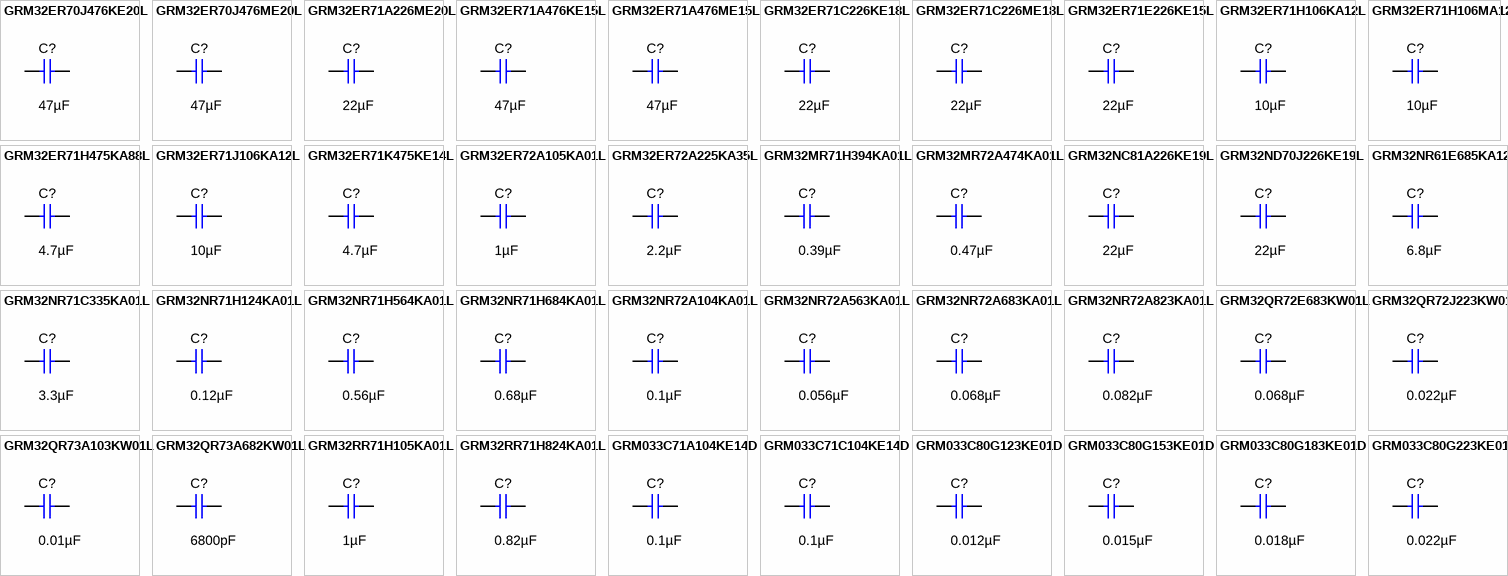
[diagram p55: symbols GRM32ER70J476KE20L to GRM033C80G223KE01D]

## GRM32ER70J476KE20L
designator C?  ValueDisplayed: 47µF  (hidden comment: GRM32ER70J476KE20L)
CAP, CERM, 47 µF, 6.3 V,+/- 10%, X7R, 1210; Manufacturer: MuRata; Polarized: N; CompType: Capacitor; Value: 47uF; U/M: EA; Cap_F: 0.000047; Tolerance_%: 10; VDC_V: 6.3; Value2: 6.3V; TaMin_C: -55; TaMax_C: 125; Cap_Case: 1210; SizeArea_mm2: 8; SizeAreaWB_mm2: 14.7; SizeX_mm: 3.2; SizeY_mm: 2.5; SizeZ_mm: 2.7; AEC Category: Q200; Green_Lifecycle: Active; Green_REACh: Passed
signal-integrity model Cap
simulation model Cap
footprint 1210_270
footprint 1210_270M
footprint 1210_270L
pins: 1, 2

## GRM32ER70J476ME20L
designator C?  ValueDisplayed: 47µF  (hidden comment: GRM32ER70J476ME20L)
CAP, CERM, 47 µF, 6.3 V,+/- 20%, X7R, 1210; Manufacturer: MuRata; Polarized: N; CompType: Capacitor; Value: 47uF; U/M: EA; Cap_F: 0.000047; Tolerance_%: 20; VDC_V: 6.3; Value2: 6.3V; TaMin_C: -55; TaMax_C: 125; Cap_Case: 1210; SizeArea_mm2: 8; SizeAreaWB_mm2: 14.7; SizeX_mm: 3.2; SizeY_mm: 2.5; SizeZ_mm: 2.7; AEC Category: Q200
signal-integrity model Cap
simulation model Cap
footprint 1210_270
footprint 1210_270M
footprint 1210_270L
pins: 1, 2

## GRM32ER71A226ME20L
designator C?  ValueDisplayed: 22µF  (hidden comment: GRM32ER71A226ME20L)
CAP, CERM, 22 µF, 10 V,+/- 10%, X7R, 1210; Manufacturer: MuRata; Polarized: N; CompType: Capacitor; Value: 22uF; U/M: EA; Cap_F: 0.000022; Tolerance_%: 10; ESR_ohm: 0.002; Value1: 0.002 ohm; Value2: 10V; IRMS_A: 3.2; TaMin_C: -55; TaMax_C: 125; Cap_Case: 1210; SizeArea_mm2: 8; SizeAreaWB_mm2: 14.7; SizeY_mm: 2.5; SizeZ_mm: 2.7; AEC Category: Q200
signal-integrity model Cap
simulation model Cap
footprint 1210_270
footprint 1210_270M
footprint 1210_270L
pins: 1, 2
